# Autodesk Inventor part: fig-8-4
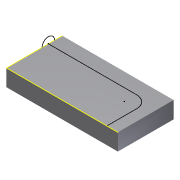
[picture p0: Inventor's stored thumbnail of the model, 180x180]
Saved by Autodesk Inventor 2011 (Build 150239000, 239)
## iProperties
Created: 2009-04
Part Number: fig-8-4
Document SubType Name: Modeling
Designer: Sham
Density: 1 g/cm^3
Author: Sham
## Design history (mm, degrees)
sketch "Sketch1"
  geometry: L1 (-20, 20)-(20, 20); L2 (20, 20)-(20, 0); L3 (20, 0)-(-20, 0); L4 (-20, 0)-(-20, 20)
  constraints: 8 end point
extrude "Extrusion1" new body sketch "Sketch1" distance "d0" = 6; taper "d1" = 0 deg
sketch "Sketch4"
  geometry: L1 (6, 0)-(6, 20) reference; C1 r 2.236 at (6, 15)
  constraints: 1 centre point, 1 point on line
sketch "Sketch5"
  geometry: L1 (-20, 0)-(-20, 20) reference; L2 (20, 0)-(-20, 0) reference; L3 (-20, 15)-(11.667, 15); L4 (16, 10.667)-(16, 0); A1 r 4.333 centre (11.667, 10.667) between (16, 10.667) and (11.667, 15)
  constraints: 4 end point, 2 point on circle, 2 point on line, 1 centre point, 1 tangent
body "Solid1"
